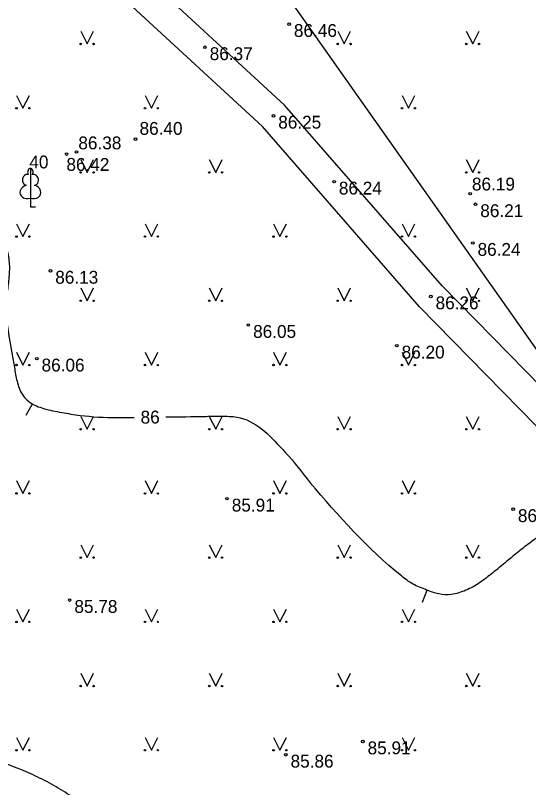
# Model space of a CAD drawing. Extents: x 576692 to 577659, y 273254 to 273799.
# Drawn here: x 577472.21 to 577492.17, y 273371.05 to 273401.11 of the extents above; entities that cross this region are included whole.
import ezdxf

# ---------------------------------------------------------------- set-up
doc = ezdxf.new("R2010")
doc.units = 0
for name, color, linetype in [('APGR_SARK_####_####_#', 7, 'Continuous'), ('ELEK_ELEM_####_####_#', 7, 'Continuous'), ('ELEK_VADP_VSPR_####_#', 7, 'Continuous'), ('GEOD_ELEM_####_TKST_#', 7, 'Continuous'), ('GEOD_SITP_####_TKST_#', 7, 'Continuous'), ('HIDT_REZV_####_TKST_#', 7, 'Continuous'), ('LKAN_ELEM_PAST_TKST_#', 7, 'Continuous'), ('RELJ_ELEM_####_####_#', 7, 'Continuous'), ('RELJ_HORZ_PAMT_####_#', 7, 'Continuous'), ('TERT_KRND_####_####_#', 7, 'Continuous')]:
    doc.layers.add(name, color=color, linetype=linetype)

msp = doc.modelspace()

# ---------------------------------------------------------------- linework, layer by layer
at = {"layer": 'ELEK_ELEM_####_####_#'}
for points in [[(577504.541, 273374.158), (577501.597, 273377.211), (577498.583, 273380.418), (577495.285, 273383.979), (577488.811, 273390.578), (577482.679, 273397.624), (577477.566, 273402.347)], [(577526.515, 273350.26), (577524.694, 273352.062), (577522.615, 273353.988), (577519.694, 273357.008), (577515.984, 273361.423), (577511.699, 273364.615), (577508.487, 273368.121), (577504.539, 273372.31), (577503.653, 273373.35), (577500.727, 273376.383), (577497.705, 273379.6), (577494.417, 273383.151), (577487.929, 273389.764), (577481.817, 273396.786), (577476.752, 273401.465)]]:
    msp.add_lwpolyline(points, dxfattribs=at)
at = {"layer": 'ELEK_VADP_VSPR_####_#'}
for centre in [(577498.474, 273401.727), (577500.973, 273398.95)]:
    msp.add_circle(centre, 50, dxfattribs=at)
at = {"layer": 'GEOD_ELEM_####_TKST_#'}
for p, q in [((577472.622, 273385.553), (577472.876, 273385.984)), ((577488.051, 273378.262), (577488.233, 273378.728))]:
    msp.add_line(p, q, dxfattribs=at)
for points in [[(577447.462, 273386.042), (577448.021, 273386.239), (577450.468, 273387.234), (577453.725, 273388.861), (577455.26, 273389.838), (577456.701, 273390.983), (577457.135, 273391.495), (577457.984, 273392.744), (577458.738, 273394.045), (577458.969, 273394.564), (577459.152, 273395.105), (577459.333, 273395.65), (577459.554, 273396.179), (577459.974, 273396.753), (577460.593, 273397.196), (577461.272, 273397.423), (577462.273, 273397.638), (577462.774, 273397.743), (577463.272, 273397.856), (577464.296, 273398.13), (577464.806, 273398.207), (577465.056, 273398.2), (577465.178, 273398.18), (577465.3, 273398.149), (577465.993, 273397.764), (577466.58, 273397.181), (577467.136, 273396.532), (577467.738, 273395.952), (577468.845, 273395.099), (577470.622, 273393.736), (577471.12, 273393.258), (577471.337, 273392.983), (577471.543, 273392.686), (577471.82, 273392.145), (577471.957, 273391.571), (577471.962, 273391), (577471.899, 273390.426), (577471.841, 273389.854), (577471.865, 273389.286), (577472.149, 273387.542), (577472.241, 273387.002), (577472.309, 273386.735), (577472.408, 273386.471), (577472.78, 273386.044), (577473.303, 273385.809), (577474.014, 273385.652), (577474.725, 273385.541), (577476.154, 273385.454), (577476.828, 273385.463)], [(577478.056, 273385.48), (577479.625, 273385.501), (577480.226, 273385.508), (577480.526, 273385.501), (577480.826, 273385.475), (577481.785, 273385.014), (577482.588, 273384.231), (577482.723, 273384.086), (577483.67, 273382.915)], [(577498.958, 273378.269), (577498.631, 273377.534), (577498.464, 273377.168), (577498.278, 273376.81), (577497.921, 273376.111), (577497.701, 273375.772), (577497.558, 273375.606), (577497.476, 273375.524), (577497.386, 273375.442), (577497.171, 273375.289), (577496.955, 273375.192), (577496.738, 273375.14), (577496.522, 273375.125), (577496.061, 273375.198), (577495.831, 273375.305), (577495.716, 273375.38), (577495.601, 273375.471), (577495.331, 273375.772), (577495.255, 273375.929), (577495.227, 273376.09), (577495.333, 273376.532), (577495.587, 273376.968), (577495.739, 273377.14), (577495.91, 273377.283), (577496.077, 273377.427), (577496.22, 273377.602), (577496.652, 273378.797), (577496.65, 273379.394), (577496.493, 273379.992), (577496.106, 273380.746), (577495.841, 273381.076), (577495.681, 273381.234), (577495.5, 273381.389), (577495.019, 273381.674), (577494.772, 273381.749), (577494.522, 273381.777), (577494.128, 273381.738), (577493.745, 273381.59), (577492.959, 273381.095), (577492.219, 273380.568), (577491.732, 273380.189), (577491.259, 273379.798), (577490.78, 273379.407), (577490.276, 273379.027), (577489.739, 273378.729), (577489.455, 273378.629), (577489.168, 273378.566), (577488.686, 273378.587), (577488.204, 273378.739), (577487.937, 273378.85), (577487.679, 273378.969), (577487.225, 273379.286), (577483.67, 273382.915)]]:
    msp.add_spline(points, degree=3, dxfattribs=at)
at = {"layer": 'GEOD_SITP_####_TKST_#'}
msp.add_spline([(577511.732, 273364.594), (577511.562, 273364.558), (577511.107, 273364.508), (577510.647, 273364.501), (577509.741, 273364.413), (577505.19, 273363.188), (577500.313, 273361.873), (577498.887, 273361.548), (577497.249, 273360.799), (577496.083, 273359.127), (577495.848, 273359.093), (577495.649, 273359.111), (577495.367, 273359.358), (577495.16, 273360.007), (577494.865, 273360.851), (577494.113, 273361.5), (577493.543, 273361.538), (577493.259, 273361.569), (577492.105, 273361.507), (577491.441, 273361.406), (577491.1, 273361.549), (577490.774, 273361.721), (577490.136, 273362.095), (577488.854, 273362.92), (577487.517, 273363.622), (577485.112, 273364.31), (577481.113, 273365.399), (577479.897, 273366.05), (577478.135, 273367.627), (577475.631, 273369.775), (577474.312, 273370.753), (577473.609, 273371.18), (577472.869, 273371.552), (577469.855, 273372.594), (577466.78, 273373.388), (577465.001, 273373.83), (577464.223, 273374.186), (577459.388, 273376.481), (577458.673, 273376.798), (577456.568, 273377.186), (577453.633, 273376.428), (577449.772, 273375.463), (577446.768, 273374.776), (577445.064, 273374.159), (577444.228, 273373.798), (577443.38, 273373.464), (577440.52, 273372.636), (577439.316, 273372.396), (577438.081, 273372.309), (577436.842, 273372.425), (577436.231, 273372.576), (577435.629, 273372.797), (577434.908, 273373.329), (577434.406, 273374.083), (577434.067, 273375.002), (577433.966, 273375.957), (577433.862, 273376.955), (577433.832, 273377.29), (577433.771, 273377.567), (577433.646, 273377.832), (577433.409, 273377.959), (577433.057, 273377.953), (577432.325, 273377.502), (577430.291, 273375.883), (577429.379, 273375.466)], degree=3, dxfattribs=at)
at = {"layer": 'LKAN_ELEM_PAST_TKST_#'}
for p, q in [((577474.75, 273400.5), (577475, 273400)), ((577475, 273400), (577475.25, 273400.5)), ((577484.75, 273400.5), (577485, 273400)), ((577485, 273400), (577485.25, 273400.5)), ((577489.75, 273400.5), (577490, 273400)), ((577490, 273400), (577490.25, 273400.5)), ((577472.25, 273398), (577472.5, 273397.5)), ((577472.5, 273397.5), (577472.75, 273398)), ((577477.25, 273398), (577477.5, 273397.5)), ((577477.5, 273397.5), (577477.75, 273398)), ((577487.25, 273398), (577487.5, 273397.5)), ((577487.5, 273397.5), (577487.75, 273398)), ((577474.75, 273395.5), (577475, 273395)), ((577475, 273395), (577475.25, 273395.5)), ((577479.75, 273395.5), (577480, 273395)), ((577480, 273395), (577480.25, 273395.5)), ((577489.75, 273395.5), (577490, 273395)), ((577490, 273395), (577490.25, 273395.5)), ((577472.789, 273394.003), (577472.789, 273393.656)), ((577472.789, 273393.656), (577472.989, 273393.656)), ((577472.25, 273393), (577472.5, 273392.5)), ((577472.5, 273392.5), (577472.75, 273393)), ((577477.25, 273393), (577477.5, 273392.5)), ((577477.5, 273392.5), (577477.75, 273393)), ((577482.25, 273393), (577482.5, 273392.5)), ((577482.5, 273392.5), (577482.75, 273393)), ((577487.25, 273393), (577487.5, 273392.5)), ((577487.5, 273392.5), (577487.75, 273393)), ((577474.75, 273390.5), (577475, 273390)), ((577475, 273390), (577475.25, 273390.5)), ((577479.75, 273390.5), (577480, 273390)), ((577480, 273390), (577480.25, 273390.5)), ((577484.75, 273390.5), (577485, 273390)), ((577485, 273390), (577485.25, 273390.5)), ((577489.75, 273390.5), (577490, 273390)), ((577490, 273390), (577490.25, 273390.5)), ((577472.25, 273388), (577472.5, 273387.5)), ((577472.5, 273387.5), (577472.75, 273388)), ((577477.25, 273388), (577477.5, 273387.5)), ((577477.5, 273387.5), (577477.75, 273388)), ((577482.25, 273388), (577482.5, 273387.5)), ((577482.5, 273387.5), (577482.75, 273388)), ((577487.25, 273388), (577487.5, 273387.5)), ((577487.5, 273387.5), (577487.75, 273388)), ((577474.75, 273385.5), (577475, 273385)), ((577475, 273385), (577475.25, 273385.5)), ((577479.75, 273385.5), (577480, 273385)), ((577480, 273385), (577480.25, 273385.5)), ((577484.75, 273385.5), (577485, 273385)), ((577485, 273385), (577485.25, 273385.5)), ((577489.75, 273385.5), (577490, 273385)), ((577490, 273385), (577490.25, 273385.5)), ((577472.25, 273383), (577472.5, 273382.5)), ((577472.5, 273382.5), (577472.75, 273383)), ((577477.25, 273383), (577477.5, 273382.5)), ((577477.5, 273382.5), (577477.75, 273383)), ((577482.25, 273383), (577482.5, 273382.5)), ((577482.5, 273382.5), (577482.75, 273383)), ((577487.25, 273383), (577487.5, 273382.5)), ((577487.5, 273382.5), (577487.75, 273383)), ((577474.75, 273380.5), (577475, 273380)), ((577475, 273380), (577475.25, 273380.5)), ((577479.75, 273380.5), (577480, 273380)), ((577480, 273380), (577480.25, 273380.5)), ((577484.75, 273380.5), (577485, 273380)), ((577485, 273380), (577485.25, 273380.5)), ((577489.75, 273380.5), (577490, 273380)), ((577490, 273380), (577490.25, 273380.5)), ((577472.25, 273378), (577472.5, 273377.5)), ((577472.5, 273377.5), (577472.75, 273378)), ((577477.25, 273378), (577477.5, 273377.5)), ((577477.5, 273377.5), (577477.75, 273378)), ((577482.25, 273378), (577482.5, 273377.5)), ((577482.5, 273377.5), (577482.75, 273378)), ((577487.25, 273378), (577487.5, 273377.5)), ((577487.5, 273377.5), (577487.75, 273378)), ((577474.75, 273375.5), (577475, 273375)), ((577475, 273375), (577475.25, 273375.5)), ((577479.75, 273375.5), (577480, 273375)), ((577480, 273375), (577480.25, 273375.5)), ((577484.75, 273375.5), (577485, 273375)), ((577485, 273375), (577485.25, 273375.5)), ((577489.75, 273375.5), (577490, 273375)), ((577490, 273375), (577490.25, 273375.5)), ((577472.25, 273373), (577472.5, 273372.5)), ((577472.5, 273372.5), (577472.75, 273373)), ((577477.25, 273373), (577477.5, 273372.5)), ((577477.5, 273372.5), (577477.75, 273373)), ((577482.25, 273373), (577482.5, 273372.5)), ((577482.5, 273372.5), (577482.75, 273373)), ((577487.25, 273373), (577487.5, 273372.5)), ((577487.5, 273372.5), (577487.75, 273373))]:
    msp.add_line(p, q, dxfattribs=at)
for points in [[(577472.789, 273395.156), (577472.789, 273394.003)], [(577472.879, 273394.924), (577472.878, 273394.925)]]:
    msp.add_lwpolyline(points, dxfattribs=at)
for centre, radius in [((577474.75, 273400), 0.028), ((577475.25, 273400), 0.0263), ((577484.75, 273400), 0.028), ((577485.25, 273400), 0.0263), ((577489.75, 273400), 0.028), ((577490.25, 273400), 0.0263), ((577472.25, 273397.5), 0.028), ((577472.75, 273397.5), 0.0263), ((577477.25, 273397.5), 0.028), ((577477.75, 273397.5), 0.0263), ((577487.25, 273397.5), 0.028), ((577487.75, 273397.5), 0.0263), ((577474.75, 273395), 0.028), ((577475.25, 273395), 0.0263), ((577479.75, 273395), 0.028), ((577480.25, 273395), 0.0263), ((577489.75, 273395), 0.028), ((577490.25, 273395), 0.0263), ((577472.25, 273392.5), 0.028), ((577472.75, 273392.5), 0.0263), ((577477.25, 273392.5), 0.028), ((577477.75, 273392.5), 0.0263), ((577482.25, 273392.5), 0.028), ((577482.75, 273392.5), 0.0263), ((577487.25, 273392.5), 0.028), ((577487.75, 273392.5), 0.0263), ((577474.75, 273390), 0.028), ((577479.75, 273390), 0.028), ((577484.75, 273390), 0.028), ((577489.75, 273390), 0.028), ((577475.25, 273390), 0.0263), ((577480.25, 273390), 0.0263), ((577485.25, 273390), 0.0263), ((577490.25, 273390), 0.0263), ((577472.25, 273387.5), 0.028), ((577472.75, 273387.5), 0.0263), ((577477.25, 273387.5), 0.028), ((577477.75, 273387.5), 0.0263), ((577482.25, 273387.5), 0.028), ((577482.75, 273387.5), 0.0263), ((577487.25, 273387.5), 0.028), ((577487.75, 273387.5), 0.0263), ((577474.75, 273385), 0.028), ((577475.25, 273385), 0.0263), ((577479.75, 273385), 0.028), ((577480.25, 273385), 0.0263), ((577484.75, 273385), 0.028), ((577485.25, 273385), 0.0263), ((577489.75, 273385), 0.028), ((577490.25, 273385), 0.0263), ((577472.25, 273382.5), 0.028), ((577472.75, 273382.5), 0.0263), ((577477.25, 273382.5), 0.028), ((577477.75, 273382.5), 0.0263), ((577482.25, 273382.5), 0.028), ((577482.75, 273382.5), 0.0263), ((577487.25, 273382.5), 0.028), ((577487.75, 273382.5), 0.0263), ((577474.75, 273380), 0.028), ((577475.25, 273380), 0.0263), ((577479.75, 273380), 0.028), ((577480.25, 273380), 0.0263), ((577484.75, 273380), 0.028), ((577485.25, 273380), 0.0263), ((577489.75, 273380), 0.028), ((577490.25, 273380), 0.0263), ((577472.25, 273377.5), 0.028), ((577472.75, 273377.5), 0.0263), ((577477.25, 273377.5), 0.028), ((577477.75, 273377.5), 0.0263), ((577482.25, 273377.5), 0.028), ((577482.75, 273377.5), 0.0263), ((577487.25, 273377.5), 0.028), ((577487.75, 273377.5), 0.0263), ((577474.75, 273375), 0.028), ((577475.25, 273375), 0.0263), ((577479.75, 273375), 0.028), ((577480.25, 273375), 0.0263), ((577484.75, 273375), 0.028), ((577485.25, 273375), 0.0263), ((577489.75, 273375), 0.028), ((577490.25, 273375), 0.0263), ((577472.25, 273372.5), 0.028), ((577472.75, 273372.5), 0.0263), ((577477.25, 273372.5), 0.028), ((577477.75, 273372.5), 0.0263), ((577482.25, 273372.5), 0.028), ((577482.75, 273372.5), 0.0263), ((577487.25, 273372.5), 0.028), ((577487.75, 273372.5), 0.0263)]:
    msp.add_circle(centre, radius, dxfattribs=at)
for centre, major_axis, ratio, start_param, end_param in [((577472.789, 273395.006), (0, -0.15), 0.707107, 3.14537, 5.287485), ((577472.789, 273395.006), (0, -0.15), 0.707107, 0.995701, 3.137816), ((577472.661, 273394.711), (-0.039, -0.212), 0.861323, 3.141593, 6.283185), ((577472.917, 273394.711), (0.039, -0.212), 0.861323, 0, 3.141593), ((577472.699, 273394.249), (0.307, 0.095), 0.814445, 1.570796, 4.752015), ((577472.879, 273394.249), (-0.307, 0.095), 0.814445, 1.531171, 4.712389)]:
    msp.add_ellipse(centre, major_axis=major_axis, ratio=ratio, start_param=start_param, end_param=end_param, dxfattribs=at)
at = {"layer": 'RELJ_ELEM_####_####_#'}
for centre in [(577482.859, 273400.775), (577479.582, 273399.873), (577482.248, 273397.205), (577476.882, 273396.295), (577474.199, 273395.714), (577474.584, 273395.795), (577484.608, 273394.639), (577489.903, 273394.173), (577490.11, 273393.759), (577490.004, 273392.252), (577473.572, 273391.167), (577488.37, 273390.171), (577481.271, 273389.057), (577487.051, 273388.253), (577473.04, 273387.748), (577480.44, 273382.295), (577491.574, 273381.886), (577474.317, 273378.348), (577485.726, 273372.843), (577482.728, 273372.325)]:
    msp.add_circle(centre, 0.05, dxfattribs=at)
at = {"layer": 'TERT_KRND_####_####_#'}
msp.add_lwpolyline([(577471.439, 273417.943), (577504.938, 273370.442), (577469.56, 273330.315), (577408.781, 273341.539), (577378.053, 273361.375), (577348.46, 273393.654), (577360.328, 273412.589)], dxfattribs=at)

# ---------------------------------------------------------------- texts
at = {"layer": 'APGR_SARK_####_####_#'}
msp.add_text(' 40', height=0.5, dxfattribs=at).set_placement((577472.564, 273395.156))
at = {"layer": 'HIDT_REZV_####_TKST_#'}
for s, p in [(' 86.46', (577482.859, 273400.275)), (' 86.37', (577479.582, 273399.373)), (' 86.40', (577476.852, 273396.464)), (' 86.25', (577482.248, 273396.705)), (' 86.38', (577474.471, 273395.899)), (' 86.42', (577474.006, 273395.061)), (' 86.24', (577484.608, 273394.139)), (' 86.19', (577489.786, 273394.296)), (' 86.21', (577490.11, 273393.259)), (' 86.24', (577490.004, 273391.752)), (' 86.13', (577473.572, 273390.667)), (' 86.26', (577488.37, 273389.671)), (' 86.05', (577481.271, 273388.557)), (' 86.20', (577487.051, 273387.753)), (' 86.06', (577473.04, 273387.248)), (' 85.91', (577480.44, 273381.795)), (' 86.15', (577491.574, 273381.386)), (' 85.78', (577474.317, 273377.848)), (' 85.91', (577485.726, 273372.343)), (' 85.86', (577482.728, 273371.825))]:
    msp.add_text(s, height=0.5, dxfattribs=at).set_placement(p)
at = {"layer": 'RELJ_HORZ_PAMT_####_#'}
msp.add_text('86', height=0.5, rotation=0.8053, dxfattribs=at).set_placement((577477.082, 273385.216))

doc.saveas('drawing.dxf')
